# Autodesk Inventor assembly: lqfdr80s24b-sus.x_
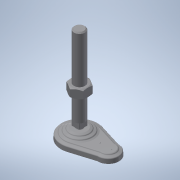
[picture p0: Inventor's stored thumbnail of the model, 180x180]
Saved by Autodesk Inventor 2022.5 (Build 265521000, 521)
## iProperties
Part Number: lqfdr80s24b-sus.x_
Material: 一般
Document SubType Name: Assembly
Designer: ImaoCorp
Sending System: SOLIDWORKS 2017-2017317
MC: AMD64
MC_MODEL: Intel64 Family 6 Model 60 Stepping 3, GenuineIntel
OS: Windows_NT
FRU: Parasolid Version 29.0, build 201,  4-17-2017
FORMAT: text
GUISE: transmit
KEY: lqfdr80s24b-sus
FILE: lqfdr80s24b-sus.x_t
DATE: Mon Jul 01 17:54:05 2019
Author: ImaoCorp
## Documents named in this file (3)
- X:\14_SW2022-Inv2022\00_全2023-1023新製品(TCC)まで\l\lqfdr80s24b-sus\LQFDR80S24B-SUS.iam
- X:\14_SW2022-Inv2022\00_全2023-1023新製品(TCC)まで\l\lqfdr80s24b-sus\lqfdr80s24b-sus_01.ipt
- X:\14_SW2022-Inv2022\00_全2023-1023新製品(TCC)まで\l\lqfdr80s24b-sus\lqfdr80s24b-sus_02.ipt
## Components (2 placed, 2 different names)
1. lqfdr80s24b-sus_01
2. lqfdr80s24b-sus_02
